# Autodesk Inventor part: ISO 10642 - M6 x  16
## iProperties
Comments: To add or edit properties for Autodesk Inventor files, use iProperties.
Created: 2004-08
Part Number: ISO 10642 - M6 x  16
Vendor: Autodesk Inc.
Document SubType Name: Modeling
Designer: John Blackburn
Material: Default
Description: Hexagon Socket Countersunk Head Screw
Standard: ISO 10642
Alert: To add or edit properties for Autodesk Inventor files, use iProperties.
Control State: 0
Master: False
Checked Out: False
Shininess: 64.0
Length Units: 11269
Angle Units: 11279
Time Units: 11290
Mass Units: 11283
Length Display Precision: 3
Angle Display Precision: 2
Compacted: True
EGR: 1
Density: 0.0
Volumn: 0.0
Area: 0.0
PropertySet Name: Model Information
Author: John Blackburn
Revision Number: 8
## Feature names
1. Body [Revolution]
2. Slot [Extrusion]
3. Chamfer1
